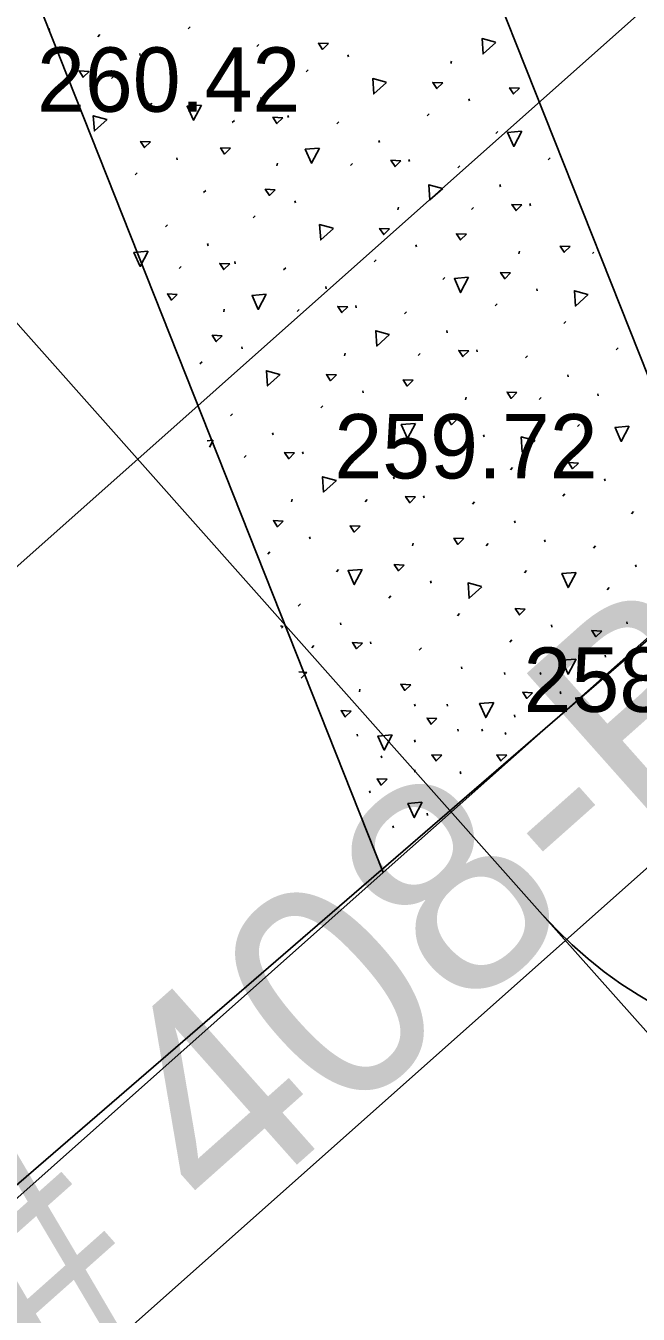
# Model space of a CAD drawing. Extents: x 49683 to 58852, y 49525 to 54803.
# Drawn here: x 55371.7 to 55400.3, y 53100.7 to 53160.7 of the extents above; entities that cross this region are included whole.
import ezdxf

# ---------------------------------------------------------------- set-up
doc = ezdxf.new("R2010")
doc.units = 0
for name, color, linetype in [('Level 11', 7, 'Continuous'), ('Level 13', 7, 'Continuous'), ('Level 15', 7, 'Continuous'), ('Level 18', 7, 'Continuous'), ('Level 19', 7, 'Continuous'), ('Level 25', 7, 'Continuous'), ('Level 32', 7, 'Continuous')]:
    doc.layers.add(name, color=color, linetype=linetype)

msp = doc.modelspace()

# ---------------------------------------------------------------- linework, layer by layer
at = {"layer": 'Level 11'}
msp.add_line((55223.521, 52979.087), (55416.975, 53146.156), dxfattribs=at)
at = {"layer": 'Level 13'}
msp.add_line((55456.917, 53171.479), (55307.435, 53038.607), dxfattribs=at)
at = {"layer": 'Level 15'}
for p, q in [((55404.292, 53135.407), (55387.03, 53178.933)), ((55388.385, 53121.267), (55371.123, 53164.793)), ((55372.826, 53160.5), (55372.803, 53160.598)), ((55375.173, 53160.311), (55375.078, 53160.213)), ((55379.389, 53160.681), (55379.294, 53160.583)), ((55382.588, 53159.856), (55382.493, 53159.758)), ((55377.064, 53159.334), (55377.04, 53159.431)), ((55386.766, 53159.281), (55386.742, 53159.378)), ((55391.541, 53158.959), (55391.571, 53159.081)), ((55375.809, 53158.367), (55375.714, 53158.268)), ((55378.464, 53158.448), (55378.441, 53158.545)), ((55384.893, 53158.678), (55384.798, 53158.579)), ((55380.811, 53158.259), (55380.716, 53158.161)), ((55382.702, 53157.282), (55382.678, 53157.379)), ((55392.404, 53157.228), (55392.38, 53157.326)), ((55377.596, 53157.111), (55377.501, 53157.012)), ((55383.968, 53156.445), (55383.945, 53156.542)), ((55390.531, 53156.626), (55390.436, 53156.527)), ((55381.447, 53156.315), (55381.352, 53156.216)), ((55386.315, 53156.256), (55386.22, 53156.157)), ((55388.206, 53155.278), (55388.182, 53155.376)), ((55393.73, 53155.801), (55393.635, 53155.703)), ((55378.785, 53154.478), (55378.761, 53154.575)), ((55383.426, 53154.205), (55383.456, 53154.327)), ((55386.951, 53154.311), (55386.856, 53154.213)), ((55389.606, 53154.393), (55389.583, 53154.49)), ((55391.953, 53154.203), (55391.858, 53154.105)), ((55396.169, 53154.574), (55396.074, 53154.475)), ((55376.912, 53153.875), (55376.817, 53153.777)), ((55380.111, 53153.05), (55380.016, 53152.952)), ((55393.844, 53153.226), (55393.82, 53153.323)), ((55384.289, 53152.475), (55384.265, 53152.572)), ((55395.245, 53152.341), (55395.221, 53152.438)), ((55382.416, 53151.872), (55382.321, 53151.774)), ((55389.064, 53152.153), (55389.094, 53152.275)), ((55392.589, 53152.259), (55392.494, 53152.161)), ((55378.334, 53151.453), (55378.239, 53151.355)), ((55380.225, 53150.476), (55380.201, 53150.573)), ((55389.927, 53150.423), (55389.903, 53150.52)), ((55394.702, 53150.101), (55394.732, 53150.223)), ((55398.203, 53150.182), (55398.132, 53150.109)), ((55378.97, 53149.509), (55378.875, 53149.41)), ((55381.491, 53149.639), (55381.467, 53149.736)), ((55383.838, 53149.45), (55383.743, 53149.352)), ((55388.054, 53149.82), (55387.959, 53149.721)), ((55391.253, 53148.995), (55391.158, 53148.897)), ((55385.729, 53148.473), (55385.705, 53148.57)), ((55395.565, 53148.37), (55395.541, 53148.468)), ((55387.129, 53147.587), (55387.106, 53147.684)), ((55393.692, 53147.768), (55393.597, 53147.669)), ((55380.949, 53147.399), (55380.978, 53147.522)), ((55384.474, 53147.506), (55384.379, 53147.407)), ((55389.476, 53147.398), (55389.381, 53147.299)), ((55396.891, 53146.943), (55396.796, 53146.845)), ((55391.367, 53146.42), (55391.343, 53146.518)), ((55381.812, 53145.669), (55381.788, 53145.766)), ((55386.587, 53145.347), (55386.617, 53145.469)), ((55390.112, 53145.453), (55390.017, 53145.355)), ((55392.767, 53145.535), (55392.744, 53145.632)), ((55395.114, 53145.345), (55395.019, 53145.247)), ((55399.33, 53145.716), (55399.235, 53145.617)), ((55379.939, 53145.066), (55379.844, 53144.968)), ((55397.005, 53144.368), (55396.981, 53144.465)), ((55387.45, 53143.617), (55387.426, 53143.714)), ((55392.225, 53143.295), (55392.255, 53143.417)), ((55395.75, 53143.401), (55395.655, 53143.303)), ((55398.406, 53143.483), (55398.382, 53143.58)), ((55385.577, 53143.014), (55385.482, 53142.916)), ((55381.361, 53142.644), (55381.266, 53142.546)), ((55388.776, 53142.189), (55388.681, 53142.091)), ((55397.537, 53142.145), (55397.442, 53142.047)), ((55383.252, 53141.667), (55383.228, 53141.764)), ((55393.088, 53141.565), (55393.064, 53141.662)), ((55391.215, 53140.962), (55391.12, 53140.863)), ((55381.997, 53140.7), (55381.902, 53140.601)), ((55384.652, 53140.781), (55384.628, 53140.878)), ((55386.999, 53140.592), (55386.904, 53140.494)), ((55394.414, 53140.137), (55394.319, 53140.039)), ((55388.89, 53139.615), (55388.866, 53139.712)), ((55398.726, 53139.513), (55398.702, 53139.61)), ((55384.11, 53138.541), (55384.14, 53138.664)), ((55387.635, 53138.648), (55387.54, 53138.549)), ((55390.29, 53138.729), (55390.267, 53138.826)), ((55392.637, 53138.54), (55392.542, 53138.441)), ((55396.853, 53138.91), (55396.758, 53138.811)), ((55400.052, 53138.085), (55399.957, 53137.987)), ((55394.528, 53137.562), (55394.504, 53137.66)), ((55384.973, 53136.811), (55384.949, 53136.908)), ((55395.928, 53136.677), (55395.905, 53136.774)), ((55383.1, 53136.208), (55383.005, 53136.11)), ((55389.748, 53136.489), (55389.778, 53136.612)), ((55393.273, 53136.595), (55393.178, 53136.497)), ((55398.275, 53136.488), (55398.18, 53136.389)), ((55400.166, 53135.51), (55400.142, 53135.608)), ((55386.299, 53135.383), (55386.204, 53135.285)), ((55388.385, 53121.267), (55404.292, 53135.407)), ((55395.06, 53135.34), (55394.965, 53135.241)), ((55390.611, 53134.759), (55390.587, 53134.856)), ((55398.911, 53134.543), (55398.816, 53134.445)), ((55384.522, 53133.786), (55384.427, 53133.688)), ((55388.738, 53134.156), (55388.643, 53134.058)), ((55391.937, 53133.331), (55391.842, 53133.233)), ((55386.413, 53132.809), (55386.389, 53132.906)), ((55396.249, 53132.707), (55396.225, 53132.804)), ((55399.757, 53132.86), (55399.733, 53132.957)), ((55387.813, 53131.923), (55387.79, 53132.02)), ((55394.376, 53132.104), (55394.281, 53132.005)), ((55385.158, 53131.842), (55385.063, 53131.743)), ((55390.16, 53131.734), (55390.065, 53131.636)), ((55398.748, 53131.307), (55398.725, 53131.405)), ((55392.051, 53130.757), (55392.027, 53130.854)), ((55394.056, 53130.492), (55394.032, 53130.59)), ((55395.723, 53130.492), (55395.7, 53130.59)), ((55387.271, 53129.684), (55387.301, 53129.806)), ((55396.654, 53129.6), (55396.631, 53129.697)), ((55389.868, 53129.018), (55389.844, 53129.115)), ((55391.38, 53129.018), (55391.356, 53129.115)), ((55394.521, 53128.513), (55394.498, 53128.61)), ((55391.884, 53127.853), (55391.861, 53127.951)), ((55393.009, 53127.853), (55392.985, 53127.951)), ((55394.095, 53127.698), (55394.071, 53127.795)), ((55387.192, 53127.621), (55387.168, 53127.718)), ((55389.868, 53127.349), (55389.844, 53127.446)), ((55388.316, 53126.611), (55388.293, 53126.709)), ((55389.868, 53125.952), (55389.844, 53126.049)), ((55392.001, 53125.874), (55391.977, 53125.971)), ((55387.774, 53124.981), (55387.75, 53125.079)), ((55390.449, 53123.934), (55390.426, 53124.031)), ((55388.859, 53123.351), (55388.836, 53123.449)), ((55298.696, 53041.543), (55388.385, 53121.267))]:
    msp.add_line(p, q, dxfattribs=at)
for points in [[(55385.832, 53159.892), (55385.557, 53159.623), (55385.367, 53159.913), (55385.832, 53159.892)], [(55393.634, 53159.95), (55393.04, 53159.414), (55392.989, 53160.126), (55393.621, 53159.955)], [(55374.676, 53158.598), (55374.401, 53158.329), (55374.212, 53158.619), (55374.676, 53158.598)], [(55388.54, 53158.089), (55387.946, 53157.552), (55387.895, 53158.264), (55388.527, 53158.093)], [(55391.158, 53158.066), (55390.883, 53157.797), (55390.694, 53158.087), (55391.158, 53158.066)], [(55394.736, 53157.819), (55394.461, 53157.55), (55394.272, 53157.84), (55394.736, 53157.819)], [(55379.91, 53157.027), (55379.535, 53156.319), (55379.244, 53156.971), (55379.896, 53157.027)], [(55375.518, 53156.359), (55374.924, 53155.823), (55374.873, 53156.535), (55375.505, 53156.364)], [(55383.706, 53156.437), (55383.431, 53156.168), (55383.242, 53156.459), (55383.706, 53156.437)], [(55394.841, 53155.809), (55394.466, 53155.102), (55394.175, 53155.754), (55394.827, 53155.809)], [(55377.539, 53155.315), (55377.264, 53155.046), (55377.075, 53155.337), (55377.539, 53155.315)], [(55381.266, 53155.014), (55380.991, 53154.745), (55380.801, 53155.036), (55381.266, 53155.014)], [(55385.414, 53155.024), (55385.039, 53154.316), (55384.748, 53154.968), (55385.4, 53155.024)], [(55389.21, 53154.434), (55388.935, 53154.165), (55388.746, 53154.456), (55389.21, 53154.434)], [(55383.355, 53153.086), (55383.08, 53152.817), (55382.89, 53153.107), (55383.355, 53153.086)], [(55391.157, 53153.144), (55390.563, 53152.608), (55390.512, 53153.32), (55391.144, 53153.149)], [(55394.848, 53152.382), (55394.573, 53152.113), (55394.384, 53152.403), (55394.848, 53152.382)], [(55386.063, 53151.283), (55385.469, 53150.746), (55385.418, 53151.458), (55386.05, 53151.287)], [(55388.681, 53151.26), (55388.406, 53150.991), (55388.217, 53151.281), (55388.681, 53151.26)], [(55392.259, 53151.013), (55391.984, 53150.744), (55391.795, 53151.035), (55392.259, 53151.013)], [(55377.433, 53150.221), (55377.058, 53149.513), (55376.767, 53150.166), (55377.419, 53150.221)], [(55397.095, 53150.438), (55396.82, 53150.169), (55396.63, 53150.46), (55397.095, 53150.438)], [(55381.229, 53149.631), (55380.954, 53149.362), (55380.765, 53149.653), (55381.229, 53149.631)], [(55392.364, 53149.003), (55391.989, 53148.296), (55391.698, 53148.948), (55392.35, 53149.003)], [(55394.319, 53149.208), (55394.045, 53148.939), (55393.855, 53149.229), (55394.319, 53149.208)], [(55378.789, 53148.209), (55378.514, 53147.939), (55378.324, 53148.23), (55378.789, 53148.209)], [(55382.936, 53148.218), (55382.562, 53147.51), (55382.27, 53148.162), (55382.923, 53148.218)], [(55397.936, 53148.2), (55397.342, 53147.663), (55397.291, 53148.376), (55397.923, 53148.205)], [(55386.733, 53147.628), (55386.458, 53147.359), (55386.268, 53147.65), (55386.733, 53147.628)], [(55388.68, 53146.339), (55388.086, 53145.802), (55388.035, 53146.514), (55388.667, 53146.343)], [(55380.878, 53146.28), (55380.603, 53146.011), (55380.413, 53146.302), (55380.878, 53146.28)], [(55392.371, 53145.576), (55392.096, 53145.307), (55391.907, 53145.598), (55392.371, 53145.576)], [(55383.586, 53144.477), (55382.992, 53143.94), (55382.941, 53144.653), (55383.573, 53144.482)], [(55386.204, 53144.454), (55385.929, 53144.185), (55385.74, 53144.475), (55386.204, 53144.454)], [(55389.782, 53144.207), (55389.507, 53143.938), (55389.317, 53144.229), (55389.782, 53144.207)], [(55394.618, 53143.632), (55394.343, 53143.363), (55394.153, 53143.654), (55394.618, 53143.632)], [(55389.887, 53142.198), (55389.512, 53141.49), (55389.221, 53142.142), (55389.873, 53142.198)], [(55391.842, 53142.402), (55391.567, 53142.133), (55391.378, 53142.423), (55391.842, 53142.402)], [(55395.459, 53141.394), (55394.865, 53140.857), (55394.814, 53141.57), (55395.446, 53141.399)], [(55399.851, 53142.061), (55399.476, 53141.354), (55399.185, 53142.006), (55399.837, 53142.061)], [(55380.175, 53141.389), (55380.445, 53141.412)], [(55380.459, 53141.412), (55380.292, 53141.095)], [(55384.256, 53140.822), (55383.981, 53140.553), (55383.791, 53140.844), (55384.256, 53140.822)], [(55397.481, 53140.35), (55397.206, 53140.081), (55397.016, 53140.371), (55397.481, 53140.35)], [(55386.202, 53139.533), (55385.608, 53138.996), (55385.558, 53139.708), (55386.189, 53139.537)], [(55389.894, 53138.77), (55389.619, 53138.501), (55389.429, 53138.792), (55389.894, 53138.77)], [(55383.727, 53137.648), (55383.452, 53137.379), (55383.263, 53137.67), (55383.727, 53137.648)], [(55387.305, 53137.401), (55387.03, 53137.132), (55386.84, 53137.423), (55387.305, 53137.401)], [(55392.14, 53136.827), (55391.865, 53136.558), (55391.676, 53136.848), (55392.14, 53136.827)], [(55389.365, 53135.596), (55389.09, 53135.327), (55388.901, 53135.618), (55389.365, 53135.596)], [(55387.409, 53135.392), (55387.035, 53134.684), (55386.743, 53135.336), (55387.396, 53135.392)], [(55397.374, 53135.256), (55396.999, 53134.548), (55396.708, 53135.2), (55397.36, 53135.256)], [(55392.982, 53134.588), (55392.388, 53134.051), (55392.337, 53134.764), (55392.969, 53134.593)], [(55395.003, 53133.544), (55394.728, 53133.275), (55394.539, 53133.565), (55395.003, 53133.544)], [(55383.596, 53132.763), (55383.712, 53132.732)], [(55383.725, 53132.727), (55383.641, 53132.65)], [(55398.567, 53132.521), (55398.292, 53132.252), (55398.102, 53132.542), (55398.567, 53132.521)], [(55387.417, 53131.964), (55387.142, 53131.695), (55386.952, 53131.986), (55387.417, 53131.964)], [(55397.377, 53131.216), (55397.002, 53130.508), (55396.711, 53131.16), (55397.363, 53131.216)], [(55384.449, 53130.613), (55384.828, 53130.596)], [(55384.828, 53130.596), (55384.56, 53130.333)], [(55389.663, 53130.021), (55389.388, 53129.752), (55389.199, 53130.042), (55389.663, 53130.021)], [(55395.348, 53129.649), (55395.073, 53129.38), (55394.883, 53129.67), (55395.348, 53129.649)], [(55393.538, 53129.198), (55393.163, 53128.49), (55392.872, 53129.142), (55393.524, 53129.198)], [(55386.888, 53128.79), (55386.613, 53128.521), (55386.424, 53128.812), (55386.888, 53128.79)], [(55390.888, 53128.446), (55390.613, 53128.177), (55390.424, 53128.467), (55390.888, 53128.446)], [(55388.806, 53127.684), (55388.432, 53126.976), (55388.14, 53127.629), (55388.793, 53127.684)], [(55391.121, 53126.738), (55390.846, 53126.469), (55390.656, 53126.76), (55391.121, 53126.738)], [(55394.146, 53126.738), (55393.871, 53126.469), (55393.681, 53126.76), (55394.146, 53126.738)], [(55388.562, 53125.613), (55388.286, 53125.344), (55388.097, 53125.634), (55388.562, 53125.613)], [(55390.203, 53124.54), (55389.828, 53123.833), (55389.537, 53124.485), (55390.189, 53124.54)]]:
    msp.add_lwpolyline(points, dxfattribs=at)
at = {"layer": 'Level 18'}
for p, q in [((55350.527, 53170.25), (55395.814, 53119.303)), ((55395.814, 53119.303), (55404.462, 53109.573))]:
    msp.add_line(p, q, dxfattribs=at)
msp.add_arc((55410.762, 53132.59), 20, 221.63337, 308.6589, dxfattribs=at)
at = {"layer": 'Level 19'}
msp.add_line((54181.768, 52078.16), (56150.851, 53828.445), dxfattribs=at)

# ---------------------------------------------------------------- texts
at = {"layer": 'Level 25'}
msp.add_text("75' R/W FILE # 408-B", height=10, rotation=41.63334, dxfattribs=at).set_placement((55310.666, 53042.148))
at = {"layer": 'Level 32'}
for s, p in [('260.42', (55372.25, 53156.718)), ('259.72', (55386.106, 53139.63)), ('258.52', (55394.923, 53128.755))]:
    msp.add_text(s, height=3, dxfattribs=at).set_placement(p)

doc.saveas('drawing.dxf')
